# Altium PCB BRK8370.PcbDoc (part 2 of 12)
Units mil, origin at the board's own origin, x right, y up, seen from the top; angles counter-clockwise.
Board outline 8267.72 x 5708.66 mil, 6 copper layers (L1-TOP, L2-GND, L3-PWR, L4-PWR, L5-GND, L6-BOT), stack 68.606 mil thick; 319 components, 516 nets, 2008 pads, 1743 vias.
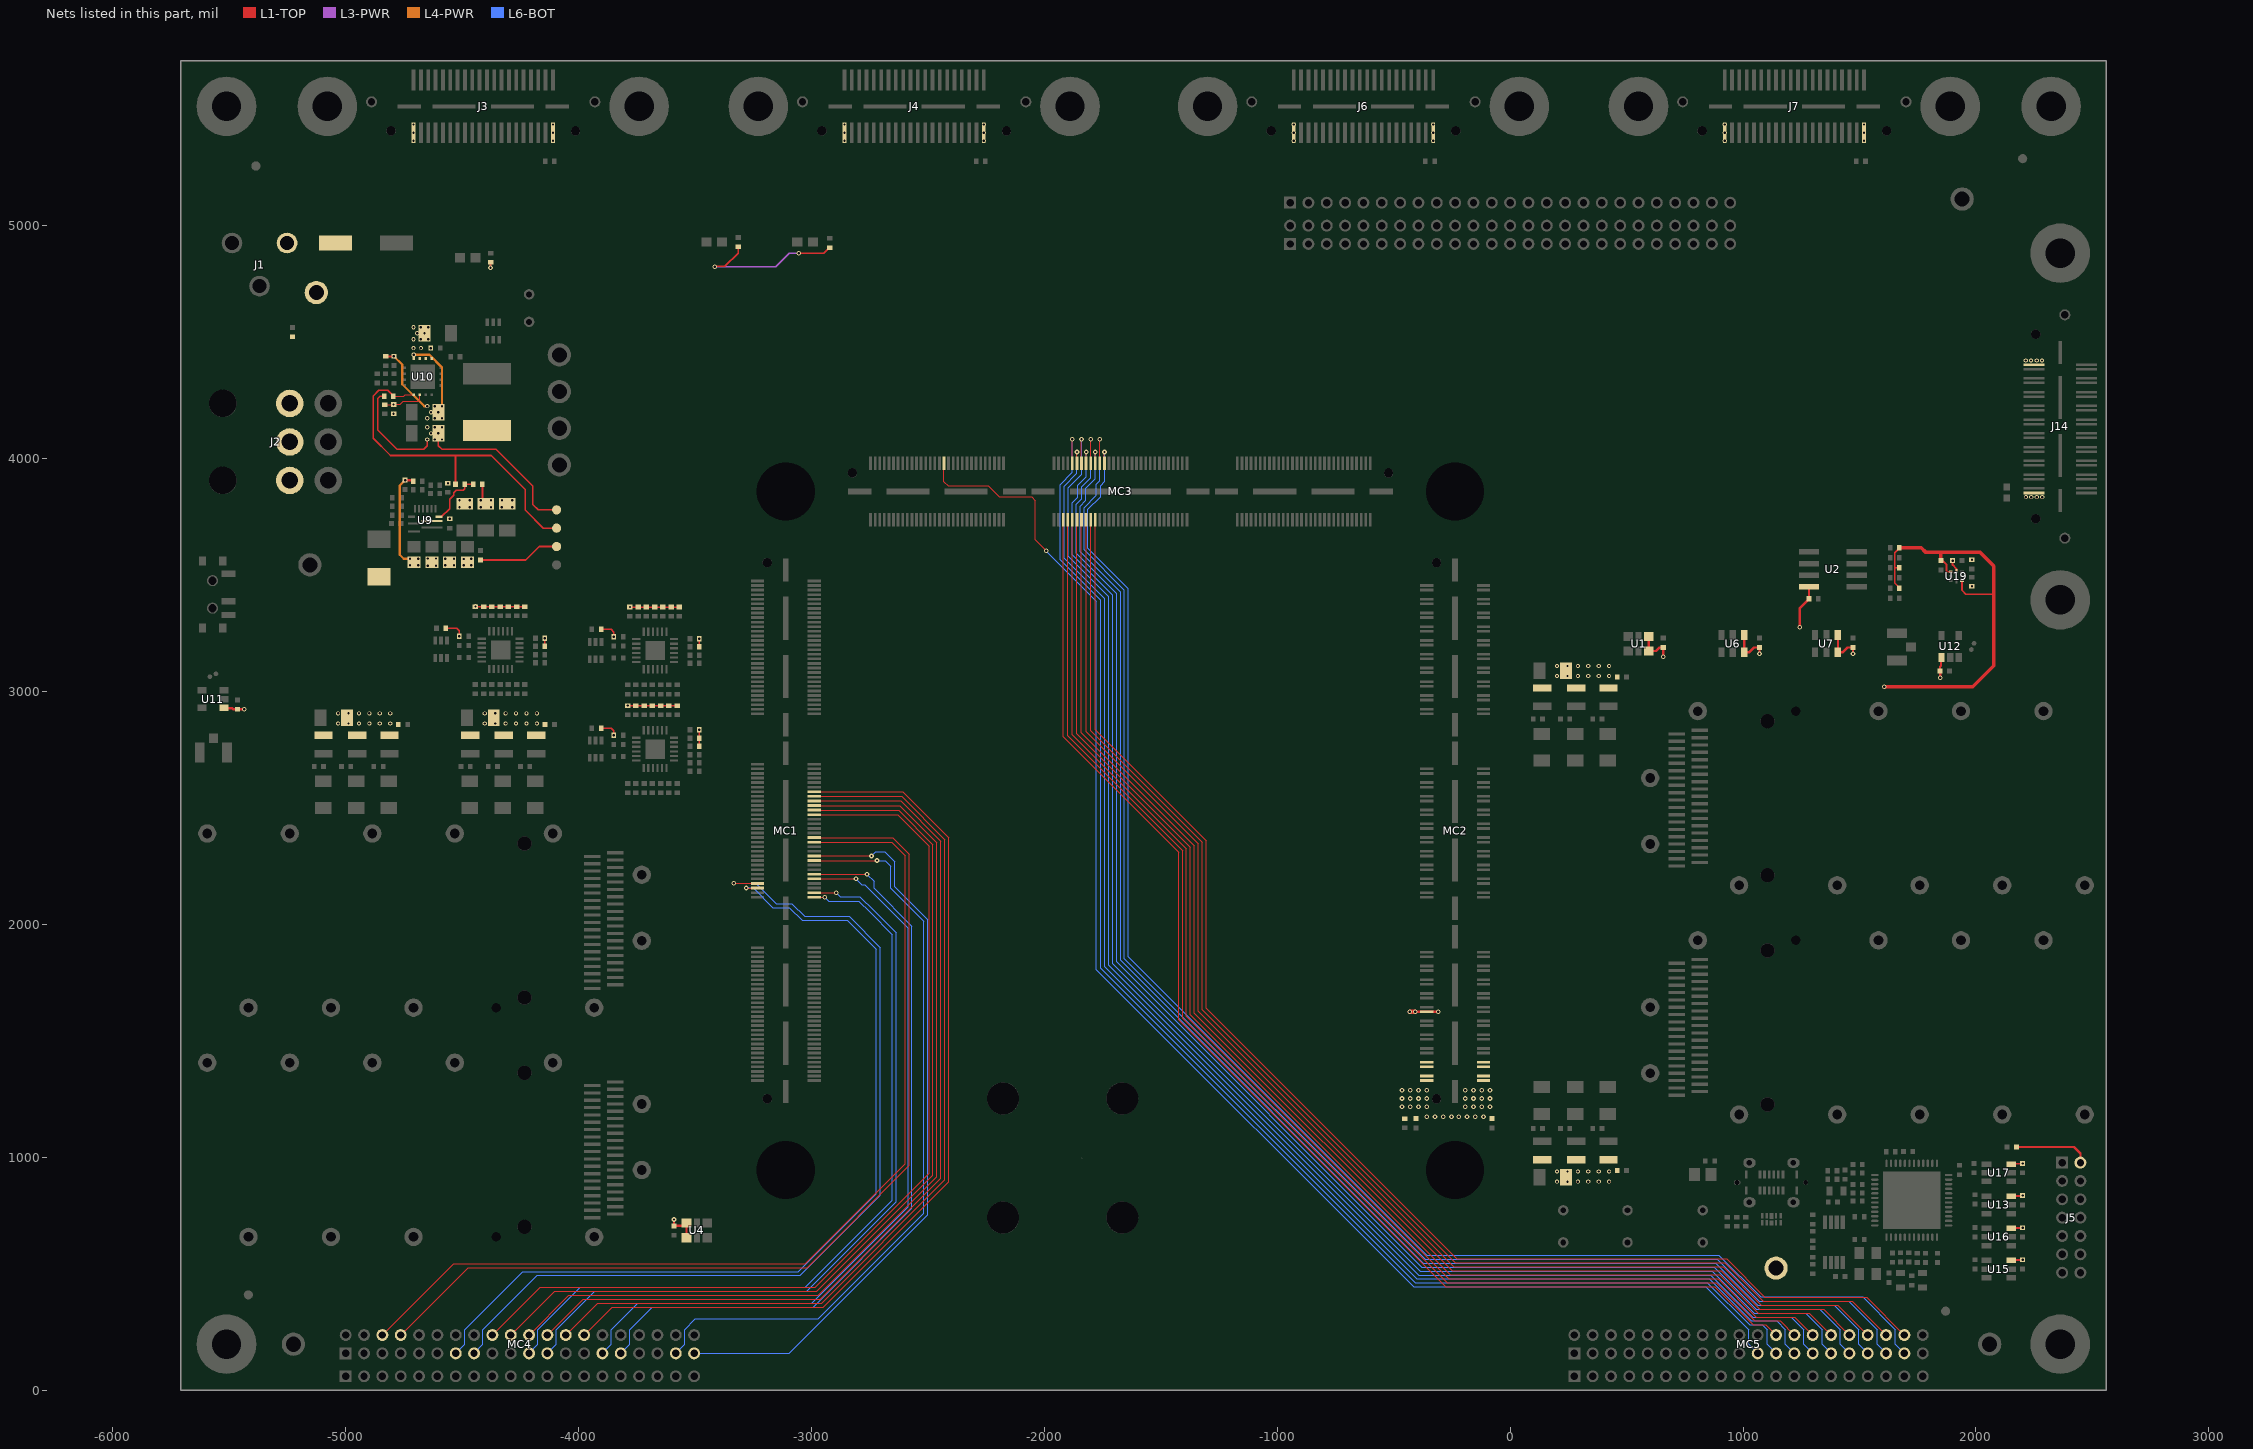
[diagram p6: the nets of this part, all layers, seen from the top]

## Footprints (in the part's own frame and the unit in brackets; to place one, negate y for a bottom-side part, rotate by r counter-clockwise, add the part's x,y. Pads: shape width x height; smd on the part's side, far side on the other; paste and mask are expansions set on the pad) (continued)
okLogo-23x5-2021 [mil] "Opal Kelly silkscreen logo (23mm x 5mm) - 2021 update"
  silkscreen extent -4,-15 672,100
OSC_SMD_32x25_6pin [mm] "3.2x2.5mm SMD clock oscillator"
  rect 0.7x1.05 smd: 1(-1.25,-0.95) 2(0,-0.95) 3(1.25,-0.95) 4(1.25,0.95) 5(0,0.95) 6(-1.25,0.95)
  silkscreen extent -1.8,-1.68 1.8,1.2
QFN-24 [mm] "QFN, 24-Leads, Body 4x4mm, Pitch 0.5mm"
  rect 2.1x2.1 smd paste-1.2: 0(0,0)
  rect 0.9x0.24 smd: 1(-2.05,1.25) 2(-2.05,0.75) 3(-2.05,0.25) 4(-2.05,-0.25) 5(-2.05,-0.75) 6(-2.05,-1.25) 13(2.05,-1.25) 14(2.05,-0.75) 15(2.05,-0.25) 16(2.05,0.25) 17(2.05,0.75) 18(2.05,1.25)
  rect 0.24x0.9 smd: 7(-1.25,-2.05) 8(-0.75,-2.05) 9(-0.25,-2.05) 10(0.25,-2.05) 11(0.75,-2.05) 12(1.25,-2.05) 19(1.25,2.05) 20(0.75,2.05) 21(0.25,2.05) 22(-0.25,2.05) 23(-0.75,2.05) 24(-1.25,2.05)
  silkscreen extent -2.69,-2.17 2.17,2.69, body extent -2.07,-2.07 2.07,2.07, height 0.8
QSE-020-01-X-D-A-L-SYZYGY [mil]
  rect 100x17 smd paste+0: 0(-317.45,0) 0(317.55,0)
  rect 185x17 smd paste+0: 0(-124.95,0) 0(125.05,0)
  rect 16x89.5 smd paste+0: 1(-299.25,-112.8) 2(-299.25,112.8) 3(-267.75,-112.8) 4(-267.75,112.8) 5(-236.25,-112.8) 6(-236.25,112.8) 7(-204.75,-112.8) 8(-204.75,112.8) 9(-173.25,-112.8) 10(-173.25,112.8) 11(-141.75,-112.8) 12(-141.75,112.8) 13(-110.25,-112.8) 14(-110.25,112.8) 15(-78.75,-112.8) 16(-78.75,112.8) 17(-47.25,-112.8) 18(-47.25,112.8) 19(-15.75,-112.8) 20(-15.75,112.8) 21(15.75,-112.8) 22(15.75,112.8) 23(47.25,-112.8) 24(47.25,112.8) 25(78.75,-112.8) 26(78.75,112.8) 27(110.25,-112.8) 28(110.25,112.8) 29(141.75,-112.8) 30(141.75,112.8) 31(173.25,-112.8) 32(173.25,112.8) 33(204.75,-112.8) 34(204.75,112.8) 35(236.25,-112.8) 36(236.25,112.8) 37(267.75,-112.8) 38(267.75,112.8) 39(299.25,-112.8) 40(299.25,112.8)
  round 47.24 hole 31.5 paste+0: MH(-479.48,-19.68) MH(479.58,-19.68)
  round 40.16 hole 40.16 unplated paste+0: MH(-396.25,105) MH(396.35,105)
  round 255.91 hole 125.98: NC(-669.24,0) NC(669.34,0)
  silkscreen extent -886,-157 885,276
QSFP28_RECEPTACLE_SFF-8679 [mm]
  rect 0.35x1.8 smd: 1(1.4,7.37) 2(2.2,7.37) 3(3,7.37) 4(3.8,7.37) 5(4.6,7.37) 6(5.4,7.37) 7(6.2,7.37) 8(7,7.37) 9(7.8,7.37) 10(8.6,7.37) 11(9.4,7.37) 12(10.2,7.37) 13(11,7.37) 14(11.8,7.37) 15(12.6,7.37) 16(13.4,7.37) 17(14.2,7.37) 18(15,7.37) 19(15.8,7.37) 20(15.4,9.88) 21(14.6,9.88) 22(13.8,9.88) 23(13,9.88) 24(12.2,9.88) 25(11.4,9.88) 26(10.6,9.88) 27(9.8,9.88) 28(9,9.88) 29(8.2,9.88) 30(7.4,9.88) 31(6.6,9.88) 32(5.8,9.88) 33(5,9.88) 34(4.2,9.88) 35(3.4,9.88) 36(2.6,9.88) 37(1.8,9.88) 38(1,9.88)
  round 1.55 hole 1.55 unplated: MH(0,0) MH(16.8,0)
  L1-TOP keep-out region: -0.5,-3.16 0.5,-3.16 0.5,-2.16 -0.5,-2.16
  L1-TOP keep-out region: 16.3,-3.16 17.3,-3.16 17.3,-2.16 16.3,-2.16
  silkscreen extent -0.8,-3 17.6,9.7
QSFP28_SINGLE_CAGE [mm]
  round 2 hole 1.05: 0(-1.1,3.1) 0(-1.1,-7.6) 0(-1.1,-16.6) 0(-1.1,-25.6) 0(-1.1,-34.6) 0(3.4,12.79) 0(10.6,12.79) 0(17.9,7.6) 0(17.9,-21.1) 0(17.9,-12.1) 0(17.9,-30.1)
  round 0 hole 1.05 unplated: 0(17.9,-3.1)
  L1-TOP keep-out region: -2.7,13.5 -2.7,-37 19.5,-37 19.5,13.5 16.5,13.5 16.5,11.1 18,11.1 18,-1.6 15.9,-1.6 15.9,-3.5 0.9,-3.5 0.9,-1.6 -1.2,-1.6 -1.2,11.1 0.3,11.1 0.3,13.5
  silkscreen extent -1.1,-48.2 17.9,12.9
QSH-020-01-X-D-DP-A-L-SYZYGY [mm]
  rect 2.54x0.43 smd mask+0.051: 0(-8.07,0) 0(8.06,0)
  rect 4.7x0.43 smd mask+0.051: 0(-3.18,0) 0(3.17,0)
  round 6.5 hole 3.2: 1(-18.909,0) 1(18.911,0)
  rect 0.28x2.27 smd mask+0.051: 1(-7.25,-2.87) 2(-7.25,2.87) 3(-6.75,-2.87) 4(-6.75,2.87) 5(-5.75,-2.87) 6(-5.75,2.87) 7(-5.25,-2.87) 8(-5.25,2.87) 9(-4.25,-2.87) 10(-4.25,2.87) 11(-3.75,-2.87) 12(-3.75,2.87) 13(-2.75,-2.87) 14(-2.75,2.87) 15(-2.25,-2.87) 16(-2.25,2.87) 17(-1.25,-2.87) 18(-1.25,2.87) 19(-0.75,-2.87) 20(-0.75,2.87) 21(0.25,-2.87) 22(0.25,2.87) 23(0.75,-2.87) 24(0.75,2.87) 25(1.75,-2.87) 26(1.75,2.87) 27(2.25,-2.87) 28(2.25,2.87) 29(3.25,-2.87) 30(3.25,2.87) 31(3.75,-2.87) 32(3.75,2.87) 33(4.75,-2.87) 34(4.75,2.87) 35(5.25,-2.87) 36(5.25,2.87) 37(6.25,-2.87) 38(6.25,2.87) 39(6.75,-2.87) 40(6.75,2.87)
  round 1.2 hole 0.8 paste+0 mask+0.076: MH(-12.18,-0.5) MH(12.18,-0.5)
  round 1.02 hole 1.02 unplated paste+0: MH(-10.07,2.67) MH(10.07,2.67)
  silkscreen extent -25,-3.99 25,7.01
QTH-060-01-X-D-DP-A [mm]
  rect 2.54x0.64 smd: 0(-28.445,0) 0(-11.555,0) 0(-8.445,0) 0(8.445,0) 0(11.555,0) 0(28.445,0)
  rect 4.7x0.64 smd: 0(-23.175,0) 0(-16.825,0) 0(-3.175,0) 0(3.175,0) 0(16.825,0) 0(23.175,0)
  rect 0.3x1.45 smd: 1(-27.25,3.09) 2(-27.25,-3.09) 3(-26.75,3.09) 4(-26.75,-3.09) 5(-25.75,3.09) 6(-25.75,-3.09) 7(-25.25,3.09) 8(-25.25,-3.09) 9(-24.25,3.09) 10(-24.25,-3.09) 11(-23.75,3.09) 12(-23.75,-3.09) 13(-22.75,3.09) 14(-22.75,-3.09) 15(-22.25,3.09) 16(-22.25,-3.09) 17(-21.25,3.09) 18(-21.25,-3.09) 19(-20.75,3.09) 20(-20.75,-3.09) 21(-19.75,3.09) 22(-19.75,-3.09) 23(-19.25,3.09) 24(-19.25,-3.09) 25(-18.25,3.09) 26(-18.25,-3.09) 27(-17.75,3.09) 28(-17.75,-3.09) 29(-16.75,3.09) 30(-16.75,-3.09) 31(-16.25,3.09) 32(-16.25,-3.09) 33(-15.25,3.09) 34(-15.25,-3.09) 35(-14.75,3.09) 36(-14.75,-3.09) 37(-13.75,3.09) 38(-13.75,-3.09) 39(-13.25,3.09) 40(-13.25,-3.09) 41(-7.25,3.09) 42(-7.25,-3.09) 43(-6.75,3.09) 44(-6.75,-3.09) 45(-5.75,3.09) 46(-5.75,-3.09) 47(-5.25,3.09) 48(-5.25,-3.09) 49(-4.25,3.09) 50(-4.25,-3.09) 51(-3.75,3.09) 52(-3.75,-3.09) 53(-2.75,3.09) 54(-2.75,-3.09) 55(-2.25,3.09) 56(-2.25,-3.09) 57(-1.25,3.09) 58(-1.25,-3.09) 59(-0.75,3.09) 60(-0.75,-3.09) 61(0.25,3.09) 62(0.25,-3.09) 63(0.75,3.09) 64(0.75,-3.09) 65(1.75,3.09) 66(1.75,-3.09) 67(2.25,3.09) 68(2.25,-3.09) 69(3.25,3.09) 70(3.25,-3.09) 71(3.75,3.09) 72(3.75,-3.09) 73(4.75,3.09) 74(4.75,-3.09) 75(5.25,3.09) 76(5.25,-3.09) 77(6.25,3.09) 78(6.25,-3.09) 79(6.75,3.09) 80(6.75,-3.09) 81(12.75,3.09) 82(12.75,-3.09) 83(13.25,3.09) 84(13.25,-3.09) 85(14.25,3.09) 86(14.25,-3.09) 87(14.75,3.09) 88(14.75,-3.09) 89(15.75,3.09) 90(15.75,-3.09) 91(16.25,3.09) 92(16.25,-3.09) 93(17.25,3.09) 94(17.25,-3.09) 95(17.75,3.09) 96(17.75,-3.09) 97(18.75,3.09) 98(18.75,-3.09) 99(19.25,3.09) 100(19.25,-3.09) 101(20.25,3.09) 102(20.25,-3.09) 103(20.75,3.09) 104(20.75,-3.09) 105(21.75,3.09) 106(21.75,-3.09) 107(22.25,3.09) 108(22.25,-3.09) 109(23.25,3.09) 110(23.25,-3.09) 111(23.75,3.09) 112(23.75,-3.09) 113(24.75,3.09) 114(24.75,-3.09) 115(25.25,3.09) 116(25.25,-3.09) 117(26.25,3.09) 118(26.25,-3.09) 119(26.75,3.09) 120(26.75,-3.09)
  round 1.02 hole 1.02 unplated: MH(-29.24,2.03) MH(29.24,2.03)
  silkscreen extent -30.05,-3.05 30.05,3.05
QTH-090-01-X-D [mm]
  rect 2.54x0.64 smd: 0(-28.445,0) 0(-11.555,0) 0(-8.445,0) 0(8.445,0) 0(11.555,0) 0(28.445,0)
  rect 4.7x0.64 smd: 0(-23.175,0) 0(-16.825,0) 0(-3.175,0) 0(3.175,0) 0(16.825,0) 0(23.175,0)
  rect 0.3x1.45 smd: 1(-27.25,3.09) 2(-27.25,-3.09) 3(-26.75,3.09) 4(-26.75,-3.09) 5(-26.25,3.09) 6(-26.25,-3.09) 7(-25.75,3.09) 8(-25.75,-3.09) 9(-25.25,3.09) 10(-25.25,-3.09) 11(-24.75,3.09) 12(-24.75,-3.09) 13(-24.25,3.09) 14(-24.25,-3.09) 15(-23.75,3.09) 16(-23.75,-3.09) 17(-23.25,3.09) 18(-23.25,-3.09) 19(-22.75,3.09) 20(-22.75,-3.09) 21(-22.25,3.09) 22(-22.25,-3.09) 23(-21.75,3.09) 24(-21.75,-3.09) 25(-21.25,3.09) 26(-21.25,-3.09) 27(-20.75,3.09) 28(-20.75,-3.09) 29(-20.25,3.09) 30(-20.25,-3.09) 31(-19.75,3.09) 32(-19.75,-3.09) 33(-19.25,3.09) 34(-19.25,-3.09) 35(-18.75,3.09) 36(-18.75,-3.09) 37(-18.25,3.09) 38(-18.25,-3.09) 39(-17.75,3.09) 40(-17.75,-3.09) 41(-17.25,3.09) 42(-17.25,-3.09) 43(-16.75,3.09) 44(-16.75,-3.09) 45(-16.25,3.09) 46(-16.25,-3.09) 47(-15.75,3.09) 48(-15.75,-3.09) 49(-15.25,3.09) 50(-15.25,-3.09) 51(-14.75,3.09) 52(-14.75,-3.09) 53(-14.25,3.09) 54(-14.25,-3.09) 55(-13.75,3.09) 56(-13.75,-3.09) 57(-13.25,3.09) 58(-13.25,-3.09) 59(-12.75,3.09) 60(-12.75,-3.09) 61(-7.25,3.09) 62(-7.25,-3.09) 63(-6.75,3.09) 64(-6.75,-3.09) 65(-6.25,3.09) 66(-6.25,-3.09) 67(-5.75,3.09) 68(-5.75,-3.09) 69(-5.25,3.09) 70(-5.25,-3.09) 71(-4.75,3.09) 72(-4.75,-3.09) 73(-4.25,3.09) 74(-4.25,-3.09) 75(-3.75,3.09) 76(-3.75,-3.09) 77(-3.25,3.09) 78(-3.25,-3.09) 79(-2.75,3.09) 80(-2.75,-3.09) 81(-2.25,3.09) 82(-2.25,-3.09) 83(-1.75,3.09) 84(-1.75,-3.09) 85(-1.25,3.09) 86(-1.25,-3.09) 87(-0.75,3.09) 88(-0.75,-3.09) 89(-0.25,3.09) 90(-0.25,-3.09) 91(0.25,3.09) 92(0.25,-3.09) 93(0.75,3.09) 94(0.75,-3.09) 95(1.25,3.09) 96(1.25,-3.09) 97(1.75,3.09) 98(1.75,-3.09) 99(2.25,3.09) 100(2.25,-3.09) 101(2.75,3.09) 102(2.75,-3.09) 103(3.25,3.09) 104(3.25,-3.09) 105(3.75,3.09) 106(3.75,-3.09) 107(4.25,3.09) 108(4.25,-3.09) 109(4.75,3.09) 110(4.75,-3.09) 111(5.25,3.09) 112(5.25,-3.09) 113(5.75,3.09) 114(5.75,-3.09) 115(6.25,3.09) 116(6.25,-3.09) 117(6.75,3.09) 118(6.75,-3.09) 119(7.25,3.09) 120(7.25,-3.09) 121(12.75,3.09) 122(12.75,-3.09) 123(13.25,3.09) 124(13.25,-3.09) 125(13.75,3.09) 126(13.75,-3.09) 127(14.25,3.09) 128(14.25,-3.09) 129(14.75,3.09) 130(14.75,-3.09) 131(15.25,3.09) 132(15.25,-3.09) 133(15.75,3.09) 134(15.75,-3.09) 135(16.25,3.09) 136(16.25,-3.09) 137(16.75,3.09) 138(16.75,-3.09) 139(17.25,3.09) 140(17.25,-3.09) 141(17.75,3.09) 142(17.75,-3.09) 143(18.25,3.09) 144(18.25,-3.09) 145(18.75,3.09) 146(18.75,-3.09) 147(19.25,3.09) 148(19.25,-3.09) 149(19.75,3.09) 150(19.75,-3.09) 151(20.25,3.09) 152(20.25,-3.09) 153(20.75,3.09) 154(20.75,-3.09) 155(21.25,3.09) 156(21.25,-3.09) 157(21.75,3.09) 158(21.75,-3.09) 159(22.25,3.09) 160(22.25,-3.09) 161(22.75,3.09) 162(22.75,-3.09) 163(23.25,3.09) 164(23.25,-3.09) 165(23.75,3.09) 166(23.75,-3.09) 167(24.25,3.09) 168(24.25,-3.09) 169(24.75,3.09) 170(24.75,-3.09) 171(25.25,3.09) 172(25.25,-3.09) 173(25.75,3.09) 174(25.75,-3.09) 175(26.25,3.09) 176(26.25,-3.09) 177(26.75,3.09) 178(26.75,-3.09) 179(27.25,3.09) 180(27.25,-3.09)
  round 1.02 hole 1.02 unplated: MH(-29.24,2.03) MH(29.24,2.03)
  silkscreen extent -30.05,-3.05 30.05,3.05
RESC1005N [mm] "Chip Resistor, Body 1.1x0.5mm, IPC Medium Density"
  rect 0.8x0.7 smd: 1(-0.6,0) 2(0.6,0)
  silkscreen extent -0.5,-0.53 0.5,0.53, body extent -0.55,-0.3 0.55,0.3, height 0.4
RESC1005X06A [mm] "Chip Resistor, 2-Leads, Body 1.00x0.50mm, OK custom footprint"
  rect 0.5x0.6 smd mask+0.051: 1(-0.5,0) 2(0.5,0)
RESC2012N [mm] "Chip Resistor, Body 2.0x1.3mm, IPC Medium Density"
  rect 1.2x1.4 smd: 1(-0.9,0) 2(0.9,0)
  silkscreen extent -0.85,-0.89 0.85,0.88, body extent -1.07,-0.7 1.07,0.7, height 0.65
RT6278 [mm]
  rect 0.8x0.23 smd: 1(-1.5,0.619) 6(1.5,0.619)
  rect 1.35x0.23 smd: 2(-1.225,-0.101) 3(-1.225,-1.001)
  rect 2.28x0.23 smd: 4(0.76,-0.551) 5(0.76,0.169)
  rect 0.23x0.8 smd: 7(1.125,1.5) 8(0.675,1.5) 9(0.225,1.5) 10(-0.225,1.5) 11(-0.675,1.5) 12(-1.125,1.5)
  silkscreen extent -2,-1.55 1.55,2
SIT9120AX-XB [mm]
  rect 1.05x1 smd: 1(-1.125,-0.8) 3(1.125,-0.8) 4(1.125,0.8) 6(-1.125,0.8)
  rect 0.65x1 smd: 2(0,-0.8) 5(0,0.8)
  silkscreen extent -1.85,-1.5 1.85,1.2
SO-G8 [mm] "Small Outline; 8 Leads; Body Width 3.9 mm; Pitch 1.27 mm"
  rect 0.6x2.2 smd: 1(-1.905,-2.6) 2(-0.635,-2.6) 3(0.635,-2.6) 4(1.905,-2.6) 5(1.905,2.6) 6(0.635,2.6) 7(-0.635,2.6) 8(-1.905,2.6)
  silkscreen extent -2.45,-3.7 2.45,1.95
SOT23-5 [mm] "SOT-23; 5 Leads; Body 2.9 x 2.5 mm, inc. leads (LxW max)"
  rect 0.7x1 smd: 1(-0.95,-1.2) 2(0,-1.2) 3(0.95,-1.2) 4(0.95,1.2) 5(-0.95,1.2)
  silkscreen extent -1.5,-1.7 1.5,0.75
SOT23-6 [mm] "SOT-23; 6 Leads; Body 3.05 x 1.75 mm, inc. leads (LxW max)"
  rect 0.6x1.05 smd: 1(-0.95,-1.35) 2(0,-1.35) 3(0.95,-1.35) 4(0.95,1.35) 5(0,1.35) 6(-0.95,1.35)
  silkscreen extent -1.5,-1.9 1.5,0.75
SOT363-6N [mm] "SOT363, 6-Leads, Body 2x1.3mm, Pitch 0.65mm, Lead Span 2.1mm, IPC Medium Density"
  rect 0.85x0.4 smd: 1(-0.95,0.65) 2(-0.95,0) 3(-0.95,-0.65) 4(0.95,-0.65) 5(0.95,0) 6(0.95,0.65)
  silkscreen extent -1.37,-1.09 0.63,1.09, body extent -0.63,-1 0.63,1, height 1
SSSS811101 [mm] "Surface mount, 1 position, 2 pole switch"
  rect 1x0.8 smd: 0(-3.65,-1.1) 0(-3.65,1.1) 0(3.65,-1.1) 0(3.65,1.1)
  round 1.2 hole 0.9: 0(-1.5,0) 0(1.5,0)
  rect 0.7x1.5 smd: 1(-2.25,1.75) 2(0.75,1.75) 3(2.25,1.75)
  silkscreen extent -3.35,-2.8 3.35,1.3
Switch-PCB-wMounts [mm]
  round 3.5 hole 3.5 unplated paste-0.02 mask+0.02: 0(-6.5,-6.5) 0(-6.5,6.5) 0(6.5,-6.5) 0(6.5,6.5)
  round 4.5 on Top Solder: 0(0,0)
  round 0.025 smd paste-1 mask-1: 1(-2.1,0) 2(2.1,0.001)
  L1-TOP region: -0.672,-1.601 -0.664,-1.639 -0.642,-1.672 -0.61,-1.693 -0.572,-1.701 -0.572,-1.701 1.016,-1.701 0.657,-1.871 0.271,-1.967 0.271,-1.967 0.214,-1.982 0.17,-2.022 0.15,-2.077 0.159,-2.136 0.193,-2.183 0.246,-2.209 0.305,-2.208 0.305,-2.208 1.28,-1.829 1.97,-1.043 2.219,-0.027 2.219,-0.027 1.993,1.009 1.306,1.817 0.32,2.206 0.32,2.206 0.262,2.208 0.21,2.184 0.174,2.139 0.163,2.082 0.178,2.026 0.217,1.984 0.271,1.963 0.271,1.963 0.659,1.87 1.021,1.7 1.021,1.7 -0.6,1.7 -0.643,1.69 -0.678,1.662 -0.697,1.622 -0.697,1.578 -0.678,1.538 -0.643,1.51 -0.6,1.5 -0.6,1.5 1.297,1.5 1.561,1.222 1.767,0.899 1.767,0.899 -1.372,0.899 -1.415,0.889 -1.45,0.861 -1.469,0.821 -1.469,0.777 -1.45,0.737 -1.415,0.709 -1.372,0.699 -1.372,0.699 1.855,0.699 1.94,0.404 1.978,0.099 1.978,0.099 -1.572,0.099 -1.615,0.089 -1.65,0.061 -1.669,0.021 -1.669,-0.023 -1.65,-0.063 -1.615,-0.091 -1.572,-0.101 -1.572,-0.101 1.977,-0.101 1.937,-0.406 1.85,-0.701 1.85,-0.701 -1.472,-0.701 -1.515,-0.711 -1.55,-0.739 -1.569,-0.779 -1.569,-0.823 -1.55,-0.863 -1.515,-0.891 -1.472,-0.901 -1.472,-0.901 1.761,-0.901 1.555,-1.224 1.291,-1.501 1.291,-1.501 -0.572,-1.501 -0.61,-1.509 -0.642,-1.53 -0.664,-1.563 -0.672,-1.601
  L1-TOP region: 1.213,-1.295 1.256,-1.285 1.291,-1.257 1.31,-1.217 1.31,-1.172 1.291,-1.132 1.256,-1.105 1.213,-1.095 1.213,-1.095 -1.648,-1.095 -1.806,-0.808 -1.915,-0.5 -1.915,-0.5 1.614,-0.5 1.657,-0.49 1.692,-0.462 1.711,-0.422 1.711,-0.378 1.692,-0.337 1.657,-0.31 1.614,-0.3 1.614,-0.3 -1.956,-0.3 -1.974,-0.153 -1.98,-0.005 -1.98,-0.005 -1.975,0.148 -1.958,0.301 -1.958,0.301 1.622,0.301 1.665,0.311 1.7,0.339 1.719,0.379 1.719,0.423 1.7,0.463 1.665,0.491 1.622,0.501 1.622,0.501 -1.917,0.501 -1.808,0.812 -1.649,1.1 -1.649,1.1 1.2,1.1 1.243,1.11 1.278,1.138 1.297,1.178 1.297,1.222 1.278,1.262 1.243,1.29 1.2,1.3 1.2,1.3 -1.497,1.3 -0.944,1.743 -0.271,1.963 -0.271,1.963 -0.217,1.984 -0.178,2.026 -0.163,2.082 -0.174,2.139 -0.21,2.184 -0.262,2.208 -0.32,2.206 -0.32,2.206 -1.306,1.817 -1.993,1.009 -2.219,-0.027 -2.219,-0.027 -1.97,-1.043 -1.28,-1.829 -0.305,-2.208 -0.305,-2.208 -0.246,-2.209 -0.193,-2.183 -0.159,-2.136 -0.15,-2.077 -0.17,-2.022 -0.214,-1.982 -0.271,-1.967 -0.271,-1.967 -0.944,-1.742 -1.497,-1.295 -1.497,-1.295
TP-PTH-25/45 [mil] "Test point, plated through-hole, 25/45mil"
  round 45 hole 25: 1(0,0)
TP-PTH-65/100 [mil] "Test point, plated through-hole, 65/100mil"
  round 100 hole 65: 1(0,0)
TP-SMD20 [mil] "Test point, surface-mount, 20mil"
  round 20 smd paste-78.74: 1(0,0)
TP-SMD40 [mm] "Test point, surface-mount, 40mil"
  round 1 smd paste-2: 1(0,0)
TPS54429E [mm]
  rect 0.3x0.3 smd paste-10 mask-10: 1(-1.975,0.975)
  rect 0.3x0.3 smd: 2(-1.975,0.325) 3(-1.975,-0.325) 4(-1.975,-0.975) 5(-0.975,-1.975) 6(-0.325,-1.975) 7(0.325,-1.975) 8(0.975,-1.975) 9(1.975,-0.975) 10(1.975,-0.325) 11(1.975,0.325) 12(1.975,0.975) 13(0.975,1.975) 14(0.325,1.975) 15(-0.325,1.975) 16(-0.975,1.975)
  rect 2.7x2.7 smd paste-10: PAD(0,0)
  L1-TOP region: 2.4,-1.15 1.725,-1.15 1.658,-1.137 1.601,-1.099 1.563,-1.042 1.55,-0.975 1.55,-0.975 1.563,-0.908 1.601,-0.851 1.658,-0.813 1.725,-0.8 1.725,-0.8 2.4,-0.8
  L1-TOP region: -2.4,1.15 -1.725,1.15 -1.658,1.137 -1.601,1.099 -1.563,1.042 -1.55,0.975 -1.55,0.975 -1.563,0.908 -1.601,0.851 -1.658,0.813 -1.725,0.8 -1.725,0.8 -2.4,0.8
  L1-TOP region: -2.4,0.5 -1.725,0.5 -1.658,0.487 -1.601,0.449 -1.563,0.392 -1.55,0.325 -1.55,0.325 -1.563,0.258 -1.601,0.201 -1.658,0.163 -1.725,0.15 -1.725,0.15 -2.4,0.15
  L1-TOP region: -2.4,-0.15 -1.725,-0.15 -1.658,-0.163 -1.601,-0.201 -1.563,-0.258 -1.55,-0.325 -1.55,-0.325 -1.563,-0.392 -1.601,-0.449 -1.658,-0.487 -1.725,-0.5 -1.725,-0.5 -2.4,-0.5
  L1-TOP region: -2.4,-0.8 -1.725,-0.8 -1.658,-0.813 -1.601,-0.851 -1.563,-0.908 -1.55,-0.975 -1.55,-0.975 -1.563,-1.042 -1.601,-1.099 -1.658,-1.137 -1.725,-1.15 -1.725,-1.15 -2.4,-1.15
  L1-TOP region: -1.15,-2.4 -1.15,-1.725 -1.137,-1.658 -1.099,-1.601 -1.042,-1.563 -0.975,-1.55 -0.975,-1.55 -0.908,-1.563 -0.851,-1.601 -0.813,-1.658 -0.8,-1.725 -0.8,-1.725 -0.8,-2.4
  L1-TOP region: -0.5,-2.4 -0.5,-1.725 -0.487,-1.658 -0.449,-1.601 -0.392,-1.563 -0.325,-1.55 -0.325,-1.55 -0.258,-1.563 -0.201,-1.601 -0.163,-1.658 -0.15,-1.725 -0.15,-1.725 -0.15,-2.4
  L1-TOP region: 0.15,-2.4 0.15,-1.725 0.163,-1.658 0.201,-1.601 0.258,-1.563 0.325,-1.55 0.325,-1.55 0.392,-1.563 0.449,-1.601 0.487,-1.658 0.5,-1.725 0.5,-1.725 0.5,-2.4
  L1-TOP region: 0.8,-2.4 0.8,-1.725 0.813,-1.658 0.851,-1.601 0.908,-1.563 0.975,-1.55 0.975,-1.55 1.042,-1.563 1.099,-1.601 1.137,-1.658 1.15,-1.725 1.15,-1.725 1.15,-2.4
  L1-TOP region: 2.4,-0.5 1.725,-0.5 1.658,-0.487 1.601,-0.449 1.563,-0.392 1.55,-0.325 1.55,-0.325 1.563,-0.258 1.601,-0.201 1.658,-0.163 1.725,-0.15 1.725,-0.15 2.4,-0.15
  L1-TOP region: 2.4,0.15 1.725,0.15 1.658,0.163 1.601,0.201 1.563,0.258 1.55,0.325 1.55,0.325 1.563,0.392 1.601,0.449 1.658,0.487 1.725,0.5 1.725,0.5 2.4,0.5
  L1-TOP region: 2.4,0.8 1.725,0.8 1.658,0.813 1.601,0.851 1.563,0.908 1.55,0.975 1.55,0.975 1.563,1.042 1.601,1.099 1.658,1.137 1.725,1.15 1.725,1.15 2.4,1.15
  L1-TOP region: 1.15,2.4 1.15,1.725 1.137,1.658 1.099,1.601 1.042,1.563 0.975,1.55 0.975,1.55 0.908,1.563 0.851,1.601 0.813,1.658 0.8,1.725 0.8,1.725 0.8,2.4
  L1-TOP region: 0.5,2.4 0.5,1.725 0.487,1.658 0.449,1.601 0.392,1.563 0.325,1.55 0.325,1.55 0.258,1.563 0.201,1.601 0.163,1.658 0.15,1.725 0.15,1.725 0.15,2.4
  L1-TOP region: -0.15,2.4 -0.15,1.725 -0.163,1.658 -0.201,1.601 -0.258,1.563 -0.325,1.55 -0.325,1.55 -0.392,1.563 -0.449,1.601 -0.487,1.658 -0.5,1.725 -0.5,1.725 -0.5,2.4
  L1-TOP region: -0.8,2.4 -0.8,1.725 -0.813,1.658 -0.851,1.601 -0.908,1.563 -0.975,1.55 -0.975,1.55 -1.042,1.563 -1.099,1.601 -1.137,1.658 -1.15,1.725 -1.15,1.725 -1.15,2.4
  L1-TOP keep-out region: -2,1.5 -1.5,1.5 -1.5,2 -2,2
  silkscreen extent -2.35,-2.1 2.1,2.35
UFL-R-SMT-1 [mm] "U.FL surface-mount coaxial connector"
  rect 1x1.05 smd paste+0: 1(0,-1.525)
  rect 1.05x2.2 smd paste+0: 2(-1.475,0) 2(1.475,0)
  silkscreen extent -1.3,-1.3 1.3,1.3
USB4120-03-C [mm]
  rect 0.3x0.87 smd: A1(-2.75,0.865) A4(-1.25,0.865) A5(-0.75,0.865) A6(-0.25,0.865) A7(0.25,0.865) A8(0.75,0.865) A9(1.25,0.865) A12(2.75,0.865) B1(2.75,-0.865) B4(1.25,-0.865) B5(0.75,-0.865) B6(0.25,-0.865) B7(-0.25,-0.865) B8(-0.75,-0.865) B9(-1.25,-0.865) B12(-2.75,-0.865)
  oval 1.35x1.1 hole 0.6 slot 0.85 at 0 deg: M1(-2.4,2.15) M2(2.4,2.15) M3(2.4,-2.15) M4(-2.4,-2.15)
  round 0.52 hole 0.52 unplated paste-20: M5(-3.75,0)
  oval 0.72x0.52 hole 0.52 slot 0.72 at 0 deg unplated paste-20: M6(3.75,0)
  silkscreen extent -4.67,-1.8 4.67,1.8
XILINX-JTAG [mm] "2mm 2x7 header"
  rect 1.3x1.3 hole 0.8: 1(-6,-1)
  round 1.3 hole 0.8: 2(-6,1) 3(-4,-1) 4(-4,1) 5(-2,-1) 6(-2,1) 7(0,-1) 8(0,1) 9(2,-1) 10(2,1) 11(4,-1) 12(4,1) 13(6,-1) 14(6,1)
  silkscreen extent -8.32,-3.15 8.32,3.15

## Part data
C1 C2 C29 C39 C45: library part 001073, "Ceramic capacitor", Manufacturer="Taiyo Yuden", Tolerance (%)=10, ValueFloat=1E-7, Voltage=25V
C3 C4 C5 C6 C8 C10 C12 C13 C15 C17 C20 C21 C23 C25 C30 C31 C32 C33 C34 C51 C52 C77 C90 C92 C95 C102 C104 C107 C112 C114: library part 000070, Manufacturer=Kemet, Manufacturer_PN=C0402C104K8PACTU, ValueFloat=1E-7, x_tolerance=10
C7: library part 000824, Manufacturer="Taiyo Yuden", ValueFloat=4.7E-6, x_tolerance=20
C9 C60 C66 C68: library part 000824, "Ceramic capacitor", Manufacturer="Taiyo Yuden", Tolerance (%)=20, ValueFloat=4.7E-6
C11 C14 C16 C18 C19 C22 C24 C26 C91 C93 C94 C103 C105 C106 C111 C113: library part 001284, Manufacturer="Taiyo Yuden", Manufacturer_PN=LMK316AB7226KL-TR, ValueFloat=2.2E-5, x_temperature_characteristic=X7R, x_tolerance=10
C27 C53: library part 000070, Manufacturer=Kemet, ValueFloat=1E-7, x_tolerance=10
C28: library part 001532, "Polarized", Manufacturer=Panasonic, ValueFloat=0.00022, Voltage=25V, x_tolerance=20, x_voltage-rating=25
C35 C36 C37: library part 001284, "Ceramic capacitor", Manufacturer="Taiyo Yuden", Tolerance (%)=10, ValueFloat=2.2E-5, Voltage=10V
C38: library part 000070, Manufacturer=Kemet, ValueFloat=1E-7, Voltage=10V, x_tolerance=10
C40: library part 002342, Manufacturer=Kemet, ValueFloat=6.8E-11, Voltage=50V, x_tolerance=5
C41 C42 C43 C44: library part 001792, Manufacturer="Samsung Electro-Mechanics", ValueFloat=2.2E-5, Voltage=6.3V, x_tolerance=20
C46: library part 002255, Manufacturer="Taiyo Yuden", ValueFloat=1E-6, Voltage=16V, x_tolerance=10, x_voltage-rating=16
C47: library part 001172, Manufacturer=TDK, ValueFloat=2.2E-5, Voltage=35V, x_tolerance=20, x_voltage-rating=35
C48: library part 001073, Manufacturer="Taiyo Yuden", ValueFloat=1E-7, Voltage=25V, x_tolerance=10
C49 C50: library part 001284, Manufacturer="Taiyo Yuden", ValueFloat=2.2E-5, Voltage=10V, x_tolerance=10
C54: library part 001297, Manufacturer=Kemet, ValueFloat=1E-11, x_tolerance=5, x_voltage-rating=50
C55: library part 001277, Manufacturer=Kemet, ValueFloat=3.3E-9, x_tolerance=10, x_voltage-rating=50
C56: library part 000480, Manufacturer="Taiyo Yuden", ValueFloat=1E-6, x_tolerance=10
C57 C58 C59 C61 C62 C63 C64 C67 C69 C70 C71 C72 C73 C74 C75 C80 C81 C82: library part 000070, Manufacturer=Kemet, Tolerance (%)=10, ValueFloat=1E-7
C65 C76: library part 000295, "Ceramic Capacitor", Manufacturer=Kemet, Tolerance (%)=10, ValueFloat=1E-8
C78 C79: library part 001640, "Ceramic capacitor", Manufacturer=Kemet, Tolerance (%)=5, ValueFloat=1.8E-11, Voltage=50
C128 C129: library part 000070, "Ceramic capacitor", Manufacturer=Kemet, Tolerance (%)=10, ValueFloat=1E-7
D1 D2 D3: library part 001433, "LED", Manufacturer=Dialight, Manufacturer_PN=598-8070-107F
D4: library part 002405, "4 channel TVS diode array", Manufacturer="Diodes Incorporated"
FB1 FB2 FB3: library part 000569, "Ferrite bead", Manufacturer=Steward, ValueFloat=600
FB4: library part 000783, "Ferrite Chip", Manufacturer=Murata, ValueFloat=220
FID1 FID2 FID3 FID4: "PCB fiducial", partnumber=ALIGNI_IGNORE
J1: library part DCPOWER, "DC power connector - high current", Manufacturer="CUI Inc.", partnumber=000356
J2: library part 001950, Manufacturer=Molex
J3 J4 J6 J7: library part 001604, "0.8mm hi-speed, high-density header (male)", Manufacturer=Samtec
J5: library part 000541, "2mm header, shrouded", Manufacturer=Molex
J8 J9 J30 J31: library part 001782, Manufacturer=Amphenol
J10 J12: library part 001335, "U.FL surface-mount coaxial connector", Manufacturer=Hirose, Manufacturer_PN=U.FL-R-SMT-1
J11: library part 002404, "USB 2.0 Type-C receptacle vertical-mount", Manufacturer=GCT
J14: library part 000694, "0.5mm Double Row High Speed Socket Assembly", Manufacturer=Samtec
J15 J16: library part 001334, Manufacturer=3M, Manufacturer_PN=951120-8622-AR
J17: library part 002533, Manufacturer=3M, Manufacturer_PN=951125-8622-AR
JP3: library part 000231, "Slide", Manufacturer=Alps
JSO1 JSO2 JSO3 JSO4: library part 001879, "Mounting hole", Manufacturer=Samtec, Manufacturer_PN=JSO-0515-01
L1 L2 L3 L4 L5 L6 L7 L8 L9 L10 L11 L12: library part 002331, "Thin Film, 1uH, 3.1A, 50mOhm, Unshielded", Manufacturer="Samsung Electro-Mechanics", Tolerance (%)=20, ValueFloat=1E-6
L13: library part 002344, Manufacturer=Sumida, ValueFloat=1.5E-6, x_tolerance=20
L14: library part 002116, Manufacturer=Murata, Manufacturer_PN=1267AY-3R3N{}P3, ValueFloat=3.3E-6, x_tolerance=30
LOGO1: library part OKLOGO, partnumber=ALIGNI_IGNORE
MC1 MC3: library part 000876, "0.5mm hi-speed, high-density header (Female)", Manufacturer=Samtec
MC2: library part 001769, Manufacturer=Samtec
MC4 MC5: library part 000583, Manufacturer=Molex
MC6: library part 002532, Manufacturer=Molex, Manufacturer_PN=0877585016
MH1 MH2 MH3 MH4: "Mounting hole", partnumber=ALIGNI_IGNORE
Q1 Q2 Q3 Q4: library part 002018, Manufacturer=Vishay
QSFP1 QSFP2 QSFP3 QSFP4: library part 001781, Manufacturer=Amphenol, Manufacturer_PN=U95-T111-1001
R1 R34 R54 R96 R103: library part 001521, "Thick-film resistor", Manufacturer=Vishay, Tolerance (%)=1, ValueFloat=10000
R2 R35 R55: library part 000964, "Thick-film resistor", Manufacturer=Vishay, Tolerance (%)=1, ValueFloat=200000
R3 R5 R6 R7 R8 R9 R68 R69 R73 R74 R76: library part 000755, Manufacturer=Vishay, ValueFloat=0, x_tolerance=1
R4 R12 R92 R102: library part 001162, "Thick-film resistor", Manufacturer=Vishay, Tolerance (%)=1, ValueFloat=2000
R10: library part 001910, "Thick-film resistor", Manufacturer=Vishay, Tolerance (%)=1, ValueFloat=5360
R11: library part 001007, "Thick-film resistor", Manufacturer=Vishay, Tolerance (%)=1, ValueFloat=4020
R13 R14 R15 R16 R17 R18 R19 R20 R21 R22 R23 R24 R28 R29 R30 R31 R32 R33 R36 R37 R38 R39 R40 R41 R42 R43 R44 R45 R46 R47 R48 R49 R50 R51 R52 R53 R56 R57 R58 R59 R60 R61 R62 R63 R80 R81 R82 R83 R84 R85 R86 R87 R88 R89 R90 R91: library part 001008, Manufacturer=Vishay, ValueFloat=4750, x_tolerance=1
R25 R26: library part 001126, Manufacturer=Vishay, ValueFloat=3010, x_tolerance=1
R27: library part 000927, "Thick-film resistor", Manufacturer=Vishay, Tolerance (%)=1, ValueFloat=2940
R64: library part 000969, Manufacturer=Vishay, ValueFloat=10, x_tolerance=1
R65: library part 000926, Manufacturer=Vishay, ValueFloat=107000, x_tolerance=1
R66: library part 000934, "Thick-film resistor", Manufacturer=Vishay, Tolerance (%)=1, ValueFloat=24900
R67: library part 001783, "Thick-film resistor", Manufacturer=Vishay, Tolerance (%)=1, ValueFloat=18700
R70: library part 001119, Manufacturer=Vishay, ValueFloat=23700, x_tolerance=1
R71: library part 002438, "NoLoad resistor", Manufacturer=Generic
R72 R75 R79: library part 001521, Manufacturer=Vishay, ValueFloat=10000, x_tolerance=1
R77: library part 001872, Manufacturer=Vishay, ValueFloat=121000, x_tolerance=1
R78: library part 002121, Manufacturer=Vishay, ValueFloat=22100, x_tolerance=1
R93 R94: library part 001919, "Thick-film resistor", Manufacturer=Vishay, Tolerance (%)=1, ValueFloat=5100
R95: library part 000826, "Thick-film resistor", Manufacturer=Vishay, Tolerance (%)=1, ValueFloat=12000
R97 R98 R99: library part 000755, "Thick-film resistor", Manufacturer=Vishay, Tolerance (%)=1, ValueFloat=0
R100 R101 R104: library part 001070, "Thick-film resistor", Manufacturer=Vishay, Tolerance (%)=1, ValueFloat=100000
S1: "Pushbutton", Manufacturer="Generic Components"
TP1 TP3 TP5 TP7 TP9 TP10 TP11 TP12 TP13 TP14: library part TP-PTH-65/100, "Test point, plated through-hole, 65/100mil", partnumber=ALIGNI_IGNORE
TP2 TP4 TP6 TP8 TP15 TP16 TP21 TP22: library part TP-PTH-25/45, "Test point, plated through-hole, 25/45mil"
TP17 TP18 TP19 TP20: library part TESTPOINT-SMD40, "Test point, surface-mount, 40mil"
TP23 TP24 TP25 TP26: "Test point, surface-mount, 20mil", partnumber=ALIGNI_IGNORE
U1 U4: library part 002434, Manufacturer=SiTime
U2: library part 002189, Manufacturer="ST Microelectronics"
U3 U5 U8: library part 002527, Manufacturer=NXP
U6 U7: library part 001712, Manufacturer="Silicon Labs"
U9: library part 002341, Manufacturer=Richtek
U10: library part 002118, "Step-down converter, 4.5 A, 7-18V input, 0.76-5.5V output, 4x4 mm", Manufacturer="Texas Instruments"
U11 U12: library part 002537, Manufacturer="ON Semiconductor"
U13 U15 U16 U17: library part 002400, "Level Translator, 0.65V - 3.6V, Direction Control", Manufacturer="Texas Instruments"
U14: library part 002398, Manufacturer=FTDI
U18: library part 002441, Manufacturer="Opal Kelly Incorporated"
U19: library part 001559, Manufacturer="ON Semiconductor"
Y1: library part 002402, "Crystal", Manufacturer=Abracon

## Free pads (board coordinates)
  round 20 hole 10 mask+2: ViaNoConnect1(-4793.25,4438.94) ViaNoConnect1(-4744.56,3906.99) ViaNoConnect1(-4707.95,4445.38)

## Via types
v1: diameter 20, hole 10, L1-TOP to L6-BOT, tented both sides, 957 vias
v2: diameter 18, hole 10, L1-TOP to L6-BOT, tented both sides, 786 vias

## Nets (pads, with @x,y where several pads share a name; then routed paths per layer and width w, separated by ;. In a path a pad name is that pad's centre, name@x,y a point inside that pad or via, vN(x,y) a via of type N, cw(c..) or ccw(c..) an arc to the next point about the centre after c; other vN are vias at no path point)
+1.8V: C4.2 C6.2 C27.2 C34.2 C51.2 C52.2 C59.2 C71.2 C75.2 C81.2 C128.2 J5.2 MC2.21 R3.2 R5.2 R6.2 TP3.1 U1.1 U1.6 U2.8 U4.1 U4.6 U6.1 U6.6 U7.1 U7.6 U13.6 U15.6 U16.6 U17.6 U19.1 U19.5 | length 3390.7
  L1-TOP w7: R6.2@1671.23,3443.67 1671.23,3445.64 1651.78,3465.08 1651.78,3530.28 ; R5.2@1671.23,3530.28 1651.78,3530.28 ; R3.2@1671.23,3616.9 1671.23,3614.93 1651.78,3595.48 1651.78,3530.28 ; U19.5@1940.16,3474.41 1940.16,3433.86 1956.69,3417.32 2076.04,3417.32
  L1-TOP w8: C128.2@1849.21,3561.42 1853.45,3557.18 1861.95,3557.18 1873.09,3546.05 1873.09,3518.47 1877.77,3513.78 U19.1@1892.52,3513.78 ; U15.6@2151.57,557.09 2152.76,558.27 2199.61,558.27 v1(2200.79,559.45) ; U16.6@2151.57,694.88 2152.76,696.06 2199.61,696.06 v1(2200.79,697.24) ; U13.6@2151.57,832.68 2152.76,833.86 2199.61,833.86 v1(2200.79,835.04) ; U17.6@2151.57,970.47 2152.76,971.65 2199.61,971.65 v1(2200.79,972.83)
  L1-TOP w10: v1(-3590.55,732.28) C34.2@-3590.55,704.72 -3548.23,704.72 U4.6@-3536.42,716.54 U4.1@-3536.42,653.54 ; U1.1@595.47,3236.22 U1.6@595.47,3173.23 625.98,3173.23 641.34,3188.58 C6.2@657.48,3188.58 v1(657.48,3149.21) ; U6.1@1005.91,3242.13 U6.6@1005.91,3167.32 1025.59,3167.32 1046.85,3188.58 C51.2@1070.87,3188.58 v1(1070.87,3161.42) ; v1(1244.09,3275.59) 1244.09,3358.07 1283.07,3397.05 C4.2@1283.07,3397.64 1283.07,3448.23 U2.8@1283.46,3448.62 ; U7.1@1407.48,3242.13 U7.6@1407.48,3167.32 1427.17,3167.32 1448.43,3188.58 C52.2@1472.44,3188.58 v1(1472.44,3161.42) ; C27.2@2174.02,1043.31 2421.26,1043.31 2448.82,1015.75 J5.2@2448.82,976.38
  L1-TOP w12: v1(-407.48,1624.02) MC2.21@-357.87,1624.02 v1(-309.06,1624.02)
  L1-TOP w15: v1(1606.3,3019.68) 1986.06,3019.68 2076.04,3109.66 2076.04,3417.32 2076.04,3538.13 2015.75,3598.43 1849.21,3598.43 ; R3.2@1671.23,3616.9 1764.99,3616.9 1783.46,3598.43 1849.21,3598.43 ; C128.2@1849.21,3561.42 1849.21,3598.43
  L1-TOP w20: v1(-431.1,1624.02) v1(-407.48,1624.02)
+3.3V_TST: C3.2 C8.2 C11.2 C12.2 C19.2 C20.2 C40.2 C41.2 C42.2 C43.2 C44.2 C45.2 C111.2 C112.2 C113.2 C114.2 C129.2 J3.40 J4.40 J6.40 J7.40 J14.40 L1.1 L2.1 L3.1 L4.1 L5.1 L6.1 L7.1 L8.1 L9.1 L10.1 L11.1 L12.1 L13.2 pad.ViaNoConnect1@-4744.56,3906.99 R1.2 R2.2 R19.2 R20.2 R21.2 R22.2 R23.2 R24.2 R25.2 R26.2 R28.2 R29.2 R34.2 R35.2 R42.2 R43.2 R44.2 R45.2 R46.2 R47.2 R52.2 R53.2 R54.2 R55.2 R65.2 R72.2 R80.2 R81.2 R82.2 R83.2 R84.2 R85.2 R86.2 R87.2 R88.2 R89.2 R90.2 R91.2 TP17.1 U11.1 U12.1 U19.8 | length 2039.6
  L1-TOP w6: R54.2@-4570.87,3271.65 -4523.62,3271.65 -4511.81,3259.84 v1(-4511.81,3236.22) ; v1(-4442.91,3364.17) R81.2@-4407.48,3364.17 R45.2@-4372.05,3364.17 R44.2@-4336.61,3364.17 R83.2@-4301.18,3364.17 R53.2@-4265.75,3364.17 R52.2@-4230.31,3364.17 ; R84.2@-4145.67,3192.91 v1(-4145.67,3228.35) ; R1.2@-3907.48,2842.52 R1.2@-3903.54,2842.52 -3860.24,2842.52 -3848.43,2830.71 v1(-3848.43,2811.02) R2.2@-3848.43,2807.09 ; R34.2@-3907.48,3265.75 R34.2@-3903.54,3265.75 -3860.24,3265.75 -3848.43,3253.94 v1(-3848.43,3234.25) R35.2@-3848.43,3230.31 ; v1(-3789.37,2938.98) R19.2@-3753.94,2938.98 R23.2@-3718.5,2938.98 R22.2@-3683.07,2938.98 R21.2@-3647.64,2938.98 R28.2@-3612.2,2938.98 R24.2@-3576.77,2938.98 ; v1(-3779.53,3362.2) R87.2@-3744.09,3362.2 R91.2@-3708.66,3362.2 R90.2@-3673.23,3362.2 R42.2@-3637.8,3362.2 R80.2@-3566.93,3362.2 ; R89.2@-3482.28,2763.78 R29.2@-3482.28,2799.21 v1(-3482.28,2834.65) ; R43.2@-3482.28,3190.94 v1(-3482.28,3226.38)
  L1-TOP w7: C45.2@-4421,3564.28 -4227.06,3564.28 -4169.29,3622.05 TP17.1@-4094.49,3622.05
  L1-TOP w8: v1(1900,3561.02) 1900,3542.91 1916.34,3526.57 U19.8@1916.34,3516.73
  L1-TOP w10: U11.1@-5522.77,2929.17 -5520.8,2927.2 -5487.34,2927.2 -5483.01,2922.87 C3.2@-5463.72,2922.87 -5463.52,2923.06 -5436.35,2923.06 v1(-5436.16,2923.26) ; C40.2@-4744.76,3907.19 -4715.52,3907.19 R65.2@-4710.44,3902.11 ; v1(1846.46,3059.06) 1846.26,3059.25 1846.26,3086.42 C8.2@1846.06,3086.61 1846.06,3105.91 1850.39,3110.24 1850.39,3143.7 U12.1@1852.36,3145.67
  L4-PWR w10: pad.ViaNoConnect1@-4744.56,3906.99 -4767.72,3883.84 -4767.72,3586.61 -4750.35,3569.24 v2(-4724.2,3569.24)
  other v1: 1983.07,3450.79 1983.07,3564.96 -4560.84,3893.67
  other v2: 201.56,894.79 246.24,894.79 290.93,894.79 335.61,894.79 380.3,894.79 424.98,894.79 201.56,938.09 246.24,938.09 290.93,938.09 335.61,938.09 380.3,938.09 424.98,938.09 -5032.48,2862.2 -4987.8,2862.2 -4943.11,2862.2 -4898.43,2862.2 -4853.74,2862.2 -4809.06,2862.2 -4402.56,2862.2 -4357.87,2862.2 -4313.19,2862.2 -4268.5,2862.2 -4223.82,2862.2 -4179.13,2862.2 -5032.48,2905.51 -4987.8,2905.51 -4943.11,2905.51 -4898.43,2905.51 -4853.74,2905.51 -4809.06,2905.51 -4402.56,2905.51 -4357.87,2905.51 -4313.19,2905.51 -4268.5,2905.51 -4223.82,2905.51 -4179.13,2905.51 201.56,3065.84 246.24,3065.84 290.93,3065.84 335.61,3065.84 380.3,3065.84 424.98,3065.84 201.56,3109.15 246.24,3109.15 290.93,3109.15 335.61,3109.15 380.3,3109.15 424.98,3109.15 -4647.2,3539.98 -4612.2,3539.98 -4724.2,3540.98 -4688.2,3540.98 -4572.2,3540.98 -4535.2,3540.98 -4461.2,3540.98 -4493.2,3541.98 -4493.2,3568.24 -4688.2,3569.24 -4572.2,3569.24 -4535.2,3569.24 -4461.2,3569.24 -4647.2,3570.24 -4612.2,3570.24 2213.87,4420.86 2236.87,4420.86 2260.87,4420.86 2283.87,4420.86 -4708.65,5364.01 -2858.26,5364.01 -929.12,5364.01 921.27,5364.01 -4708.65,5399.01 -2858.26,5399.01 -929.12,5399.01 921.27,5399.01 -4708.65,5434.01 -2858.26,5434.01 -929.12,5434.01 921.27,5434.01
+3.3V_TST_EN: R69.1 R74.1 U9.6 | length 246.3
  L1-TOP w6: U9.6@-4599.56,3749.98 -4588.99,3749.98 -4554.11,3784.86 -4554.11,3824.79 -4535.89,3843.02 -4535.89,3853.56 -4525.05,3864.39 -4495.72,3864.39 -4489.16,3870.95 -4489.16,3889.21 R74.1@-4489.2,3889.25 ; R74.1@-4489.94,3889.7 -4452.65,3889.7 R69.1@-4452.2,3889.25
+5V_TST: C49.2 C50.2 C54.2 J3.2 J4.2 J6.2 J7.2 J14.2 L14.2 pad.ViaNoConnect1@-4707.95,4445.38 pad.ViaNoConnect1@-4793.25,4438.94 R77.2 R79.2 TP19.1 U10.16 | length 1795.3
  L1-TOP w7: R79.2@-4834.94,4266.87 -4852.73,4266.87 -4862.2,4257.39 -4862.2,4122.05 -4779.53,4039.37 -4665.35,4039.37 -4649.91,4054.82 v2(-4649.91,4081.87) ; v2(-4602.17,4107.87) -4602.17,4054.92 -4586.7,4039.45 -4354.42,4039.45 -4196.85,3881.89 -4196.85,3802.63 -4173.75,3779.53 TP19.1@-4094.49,3779.53
  L1-TOP w8: R77.2@-4829.25,4438.55 -4793.65,4438.55 pad.ViaNoConnect1@-4793.25,4438.94
  L4-PWR w10: pad.ViaNoConnect1@-4793.25,4438.94 -4757.25,4402.94 -4757.25,4319.13 -4662.99,4224.87 v2(-4649.91,4224.87) ; pad.ViaNoConnect1@-4708.15,4445.18 -4640.57,4445.18 -4586.25,4390.87 v2(-4586.25,4224.87)
  other v2: 2214.56,3834.16 2237.56,3834.16 2261.56,3834.16 2284.56,3834.16 -4618.08,4081.87 -4586.25,4081.87 -4633.99,4107.87 -4649.91,4133.87 -4618.08,4133.87 -4586.25,4133.87 -4649.91,4172.87 -4618.08,4172.87 -4586.25,4172.87 -4633.99,4198.87 -4602.17,4198.87 -4618.08,4224.87 -4110.15,5364.01 -2259.76,5364.01 -330.62,5364.01 1519.77,5364.01 -4110.15,5399.01 -2259.76,5399.01 -330.62,5399.01 1519.77,5399.01 -4110.15,5434.01 -2259.76,5434.01 -330.62,5434.01 1519.77,5434.01
+5V_TST_EN: R75.1 R76.1 U10.6 | length 180
  L1-TOP w4.96: R76.1@-4831.42,4231.57 -4794.87,4231.57 v2(-4794.57,4231.87)
  L1-TOP w5: v2(-4794.57,4231.87) -4766.25,4231.87 -4753.25,4244.87 -4688.25,4244.87 -4682.09,4251.03 U10.6@-4682.09,4273.62
+5V_TST_PGOOD: R74.2 R79.1 TP20.1 U10.5 | length 1504
  L1-TOP w5: R79.1@-4795.57,4266.87 -4751.25,4266.87 -4744.5,4273.62 U10.5@-4707.68,4273.62
  L1-TOP w7: R79.1@-4795.57,4266.87 -4795.57,4268.83 -4819.36,4292.62 -4857.91,4292.62 -4881.89,4268.64 -4881.89,4086.61 -4808.07,4012.8 -4527.56,4012.8 ; R74.2@-4528.57,3889.25 -4528.57,4011.79 -4527.56,4012.8 ; TP20.1@-4094.49,3700.79 -4151.74,3700.79 -4228.35,3777.39 -4228.35,3866.14 -4375,4012.8 -4527.56,4012.8
+VDCIN: C1.1 C2.1 C28.1 C29.2 C35.2 C36.2 C37.2 C38.2 C47.2 C48.2 J1.1 J2.1 J2.2 J2.3 MC2.1 MC2.2 MC2.3 MC2.4 MC2.5 MC2.6 MC2.7 MC2.8 R4.2 R12.2 R69.2 R75.2 R92.2 R104.2 TP1.1 U9.5 U10.13 U10.14 U10.15 | length 792.3
  L1-TOP w6: v1(-3414.89,4823.73) -3414.12,4824.49 -3372.36,4824.49 -3314.96,4881.89 R12.2@-3314.96,4909.45 ; v1(-3055.12,4881.89) -2946.85,4881.89 -2923.23,4905.51 R92.2@-2921.26,4905.51
  L1-TOP w8: R69.2@-4412.83,3889.25 -4412.83,3820.34 C36.2@-4398.2,3805.72 ; v1(-4377.95,4818.9) R4.2@-4377.95,4842.52
  L3-PWR w6: v1(-3414.89,4823.73) -3152.65,4823.73 -3094.49,4881.89 v1(-3055.12,4881.89)
  other v1: -358.27,1173.23 -322.83,1173.23 -287.4,1173.23 -251.97,1173.23 -220.47,1173.23 -185.04,1173.23 -149.61,1173.23 -114.17,1173.23 -464.57,1216.54 -429.13,1216.54 -393.7,1216.54 -358.27,1216.54 -192.91,1216.54 -157.48,1216.54 -122.05,1216.54 -86.61,1216.54 -464.57,1251.97 -429.13,1251.97 -393.7,1251.97 -358.27,1251.97 -192.91,1251.97 -157.48,1251.97 -122.05,1251.97 -86.61,1251.97 -464.57,1287.4 -429.13,1287.4 -393.7,1287.4 -358.27,1287.4 -192.91,1287.4 -157.48,1287.4 -122.05,1287.4 -86.61,1287.4 -4553.27,3741.04
  other v2: -4511.62,3790.32 -4467.62,3790.32 -4420.41,3790.32 -4376.41,3790.32 -4329.25,3790.41 -4285.25,3790.41 -4511.2,3821.11 -4467.2,3821.11 -4419.99,3821.11 -4375.99,3821.11 -4328.83,3821.2 -4284.83,3821.2 -4794.57,4192.5 -4709.08,4473.87 -4677.25,4473.87 -4634.33,4473.87 -4709.08,4511.87 -4677.25,4511.87 -4645.43,4511.87 -4693.17,4537.87 -4661.34,4537.87 -4709.08,4563.87 -4677.25,4563.87 -4645.43,4563.87
B64_L1N: MC3.79 MC5.33 | length 6275.1
  L1-TOP w4.96: MC3.79@-1781.77,3979.65 MC3.79@-1781.5,3979.92 -1781.5,4027.82 v1(-1781.23,4028.09)
  L6-BOT w4.96: v1(-1781.23,4028.09) -1781.23,3913.07 -1822.77,3871.53 -1822.77,3819.7 -1846.75,3795.72 -1846.75,3600.55 -1675.03,3428.83 -1675.03,1847.52 -372.32,544.81 844.95,544.81 882.52,544.81 1062.99,364.34 1391.91,364.34 1497.24,259.01 1497.24,195.67 MC5.33@1535.43,157.48
B64_L1P: MC3.77 MC5.31 | length 6324.2
  L1-TOP w4.96: MC3.77@-1801.45,3979.65 -1801.72,3979.92 -1801.72,4081.25 v1(-1801.03,4081.95)
  L6-BOT w4.96: v1(-1801.03,4081.95) -1801.03,3917.26 -1839.73,3878.55 -1839.73,3826.72 -1863.71,3802.74 -1863.71,3593.53 -1691.99,3421.81 -1691.99,1840.5 -379.35,527.85 842.23,527.85 875.49,527.85 1055.97,347.38 1330.13,347.38 1418.5,259.01 1418.5,195.67 MC5.31@1456.69,157.48
B64_L5N: MC3.75 MC5.29 | length 6157.5
  L1-TOP w4.96: MC3.75@-1821.14,3979.65 MC3.75@-1820.87,3979.92 -1820.87,4027.82 v1(-1820.6,4028.09)
  L6-BOT w4.96: v1(-1820.6,4028.09) -1820.6,3921.68 -1856.7,3885.58 -1856.7,3833.75 -1880.67,3809.77 -1880.67,3586.5 -1708.95,3414.78 -1708.95,1833.47 -386.37,510.89 831.63,510.89 868.47,510.89 1048.94,330.42 1268.35,330.42 1339.76,259.01 1339.76,195.67 MC5.29@1377.95,157.48
B64_L5P: MC3.73 MC5.27 | length 6206.6
  L1-TOP w4.96: MC3.73@-1840.82,3979.65 -1841.09,3979.92 -1841.09,4081.25 v1(-1840.4,4081.95)
  L6-BOT w4.96: v1(-1840.4,4081.95) -1840.4,3931.26 -1897.64,3874.02 -1897.64,3579.47 -1725.92,3407.75 -1725.92,1826.44 -393.4,493.93 840.72,493.93 861.44,493.92 1041.91,313.45 1206.57,313.45 1261.02,259.01 1261.02,195.67 MC5.27@1299.21,157.48
B64_L6N: MC3.71 MC5.25 | length 6039.9
  L1-TOP w4.96: MC3.71@-1860.51,3979.65 MC3.71@-1860.24,3979.92 -1860.24,4027.82 v1(-1859.97,4028.09)
  L6-BOT w4.96: v1(-1859.97,4028.09) -1859.97,3935.68 -1914.6,3881.04 -1914.6,3815.81 -1914.6,3572.45 -1742.88,3400.73 -1742.88,1819.42 -400.43,476.96 854.42,476.96 1034.89,296.49 1144.8,296.49 1182.28,259.01 1182.28,195.67 MC5.25@1220.47,157.48
B64_L6P: MC3.69 MC5.23 | length 6089
  L1-TOP w4.96: MC3.69@-1880.19,3979.65 -1880.46,3979.92 -1880.46,4081.25 v1(-1879.77,4081.95)
  L6-BOT w4.96: v1(-1879.77,4081.95) -1879.77,3939.87 -1931.56,3888.07 -1931.56,3808.78 -1931.56,3565.42 -1759.84,3393.7 -1759.84,1812.39 -407.45,460 819.53,460 847.39,460 1027.86,279.53 1083.02,279.53 1103.54,259.01 1103.54,195.67 MC5.23@1141.73,157.48
B64_L7N: MC3.83 MC5.37 | length 6394.1
  L1-TOP w4.96: MC3.83@-1742.4,3979.65 MC3.83@-1742.13,3979.92 -1742.13,4027.82 v1(-1741.86,4028.09)
  L6-BOT w4.96: v1(-1741.86,4028.09) -1740.16,4026.39 -1740.16,3901.2 -1757.74,3883.62 -1757.74,3836.75 -1812.82,3781.67 -1812.82,3614.61 -1641.1,3442.89 -1641.1,1861.57 -358.27,578.74 870.08,578.74 896.57,578.74 1075.72,399.59 1514.14,399.59 1654.72,259.01 1654.72,195.67 MC5.37@1692.91,157.48
B64_L7P: MC3.81 MC5.35 | length 6441.7
  L1-TOP w4.96: MC3.81@-1762.08,3979.65 -1762.35,3979.92 -1762.35,4081.25 v1(-1761.66,4081.95)
  L6-BOT w4.96: v1(-1761.66,4081.95) -1761.66,3903.69 -1776.39,3888.95 -1776.39,3842.09 -1829.79,3788.69 -1829.79,3607.58 -1658.06,3435.86 -1658.06,1854.55 -365.29,561.78 855.55,561.78 889.55,561.78 1069.36,381.97 1453.02,381.97 1575.98,259.01 1575.98,195.67 MC5.35@1614.17,157.48
B64_L9N: MC3.68 MC5.26 | length 5534.4
  L1-TOP w4.96: MC3.68@-1899.61,3736.61 -1899.61,2809.53 -1406.68,2316.6 -1406.68,1597.39 -270.5,461.21 885.98,461.21 1050.73,296.46 1160.23,296.46 MC5.26@1220.47,236.22
B64_L9P: MC3.66 MC5.24 | length 5477.8
  L1-TOP w4.96: MC3.66@-1919.29,3736.61 -1919.29,2805.22 -1423.64,2309.57 -1423.64,1590.36 -277.53,444.25 870.71,444.25 878.95,444.25 1043.7,279.5 1098.45,279.5 MC5.24@1141.73,236.22
B64_L16N: MC3.76 MC5.34 | length 5760.5
  L1-TOP w4.96: MC3.76@-1820.87,3736.61 -1820.87,2826.74 -1338.83,2344.7 -1338.83,1625.5 -242.4,529.07 914.08,529.07 1078.83,364.31 1407.34,364.31 MC5.34@1535.43,236.22
B64_L16P: MC3.74 MC5.32 | length 5704
  L1-TOP w4.96: MC3.74@-1840.55,3736.61 -1840.55,2822.44 -1355.79,2337.68 -1355.79,1618.47 -249.43,512.1 885.53,512.1 907.05,512.1 1071.8,347.35 1345.56,347.35 MC5.32@1456.69,236.22
B64_L18N: MC3.72 MC5.30 | length 5647.4
  L1-TOP w4.96: MC3.72@-1860.24,3736.61 -1860.24,2818.13 -1372.75,2330.65 -1372.75,1611.44 -256.45,495.14 900.03,495.14 1064.78,330.39 1283.78,330.39 MC5.30@1377.95,236.22
B64_L18P: MC3.70 MC5.28 | length 5590.9
  L1-TOP w4.96: MC3.70@-1879.92,3736.61 -1879.92,2813.83 -1389.72,2323.63 -1389.72,1604.42 -263.48,478.18 852.53,478.18 893,478.18 1057.75,313.43 1222.01,313.43 MC5.28@1299.21,236.22
B64_L20N: MC3.80 MC5.38 | length 5873.6
  L1-TOP w4.96: MC3.80@-1781.5,3736.61 -1781.5,2835.35 -1573.84,2627.69 -1304.9,2358.76 -1304.9,1639.55 -228.35,562.99 929.5,562.99 1094.25,398.24 1530.89,398.24 MC5.38@1692.91,236.22
B64_L20P: MC3.78 MC5.36 | length 5817
  L1-TOP w4.96: MC3.78@-1801.18,3736.61 -1801.18,2831.05 -1321.87,2351.73 -1321.87,1632.52 -235.37,546.03 922.48,546.03 1087.23,381.28 1469.12,381.28 MC5.36@1614.17,236.22
B64_T0U_N12_VRP: MC3.33 MC5.21 | length 6187.2
  L1-TOP w4.96: MC3.33@-2431.1,3979.92 -2431.1,3899.61 -2413.39,3881.89 -2240.16,3881.89 -2192.91,3834.65 -2055.12,3834.65 -2039.37,3818.9 -2039.37,3650.28 v1(-1992.35,3603.26)
  L6-BOT w4.96: v1(-1992.35,3603.26) -1992.35,3602.22 -1776.81,3386.67 -1776.81,1805.36 -414.48,443.04 840.36,443.04 1024.39,259.01 1024.8,259.01 1024.8,195.67 MC5.21@1062.99,157.48
B68_L1N: MC1.108 MC4.28 | length 3974.7
  L1-TOP w4.96: MC4.28@-3976.38,236.22 -3856.13,356.47 -2948.88,356.47 -2410.41,894.94 -2410.41,2370.5 -2608.81,2568.9 -2935.44,2568.9 MC1.108@-2988.58,2568.9
B68_L1P: MC1.106 MC4.26 | length 4003.2
  L1-TOP w4.96: MC4.26@-4055.12,236.22 -3917.91,373.43 -2955.91,373.43 -2427.38,901.97 -2427.38,2363.47 -2613.12,2549.21 -2935.44,2549.21 MC1.106@-2988.58,2549.21
B68_L2N: MC1.104 MC4.24 | length 4031.6
  L1-TOP w4.96: MC4.24@-4133.86,236.22 -3979.68,390.39 -2962.94,390.39 -2444.34,908.99 -2444.34,2356.44 -2617.42,2529.53 -2935.44,2529.53 MC1.104@-2988.58,2529.53
B68_L2P: MC1.102 MC4.22 | length 4060
  L1-TOP w4.96: MC4.22@-4212.6,236.22 -4041.46,407.36 -2969.96,407.36 -2461.3,916.02 -2461.3,2349.42 -2621.73,2509.84 -2935.44,2509.84 MC1.102@-2988.58,2509.84
B68_L3N: MC1.88 MC4.8 | length 4259
  L1-TOP w4.96: MC4.8@-4763.78,236.22 -4473.9,526.1 -3019.15,526.1 -2580.04,965.2 -2580.04,2300.23 -2651.86,2372.05 -2935.44,2372.05 MC1.88@-2988.58,2372.05
B68_L3P: MC1.86 MC4.6 | length 4287.4
  L1-TOP w4.96: MC4.6@-4842.52,236.22 -4535.68,543.06 -3026.17,543.06 -2597.01,972.23 -2597.01,2293.21 -2656.16,2352.36 -2935.44,2352.36 MC1.86@-2988.58,2352.36
B68_L6N: MC1.100 MC4.20 | length 4088.4
  L1-TOP w4.96: MC4.20@-4291.34,236.22 -4103.24,424.32 -2976.99,424.32 -2478.26,923.05 -2478.26,2342.39 -2626.03,2490.16 -2935.44,2490.16 MC1.100@-2988.58,2490.16
B68_L6P: MC1.98 MC4.18 | length 4116.9
  L1-TOP w4.96: MC4.18@-4370.08,236.22 -4165.02,441.28 -2984.02,441.28 -2495.23,930.07 -2495.23,2335.36 -2630.33,2470.47 -2935.44,2470.47 MC1.98@-2988.58,2470.47
B68_L7N: MC1.72 MC4.31 | length 3286.7
  L1-TOP w4.96: MC1.72@-2988.58,2214.57 v1(-2761.81,2214.57)
  L6-BOT w4.96: MC4.31@-3818.9,157.48 -3780.7,195.67 -3780.7,259.01 -3683.53,356.18 -2992.64,356.18 -2568.39,780.43 -2568.39,1990.85 -2731.52,2153.98 -2731.52,2184.28 v1(-2761.81,2214.57)
B68_L7P: MC1.70 MC4.29 | length 3297.4
  L1-TOP w4.96: MC1.70@-2988.58,2194.88 v1(-2809.06,2194.88)
  L6-BOT w4.96: MC4.29@-3897.64,157.48 -3859.44,195.67 -3859.44,259.01 -3745.31,373.15 -2999.66,373.15 -2585.35,787.46 -2585.35,1983.83 -2770.82,2169.29 -2783.46,2169.29 v1(-2809.06,2194.88)
B68_L8N: MC1.80 MC4.39 | length 3195.5
  L1-TOP w4.96: MC1.80@-2988.58,2293.31 v1(-2742.13,2293.31)
  L6-BOT w4.96: MC4.39@-3503.94,157.48 -3095.38,157.48 -2500.54,752.33 -2500.54,2018.96 -2642.36,2160.79 -2642.36,2268.41 -2684.6,2310.65 -2724.78,2310.65 v1(-2742.13,2293.31)
B68_L8P: MC1.78 MC4.37 | length 3239.7
  L1-TOP w4.96: MC1.78@-2988.58,2273.62 v1(-2718.5,2273.62)
  L6-BOT w4.96: MC4.37@-3582.68,157.48 -3544.48,195.67 -3544.48,259.01 -3498.2,305.29 -2971.56,305.29 -2517.5,759.35 -2517.5,2011.93 -2659.33,2153.76 -2659.33,2249.46 -2683.48,2273.62 v1(-2718.5,2273.62)
B68_L9N: MC1.67 MC4.15 | length 3972.8
  L1-TOP w4.96: v1(-3333.92,2175.89) -3333.22,2175.2 MC1.67@-3231.89,2175.2 MC1.67@-3231.62,2175.47
  L6-BOT w4.96: MC4.15@-4448.82,157.48 -4410.63,195.67 -4410.63,259.01 -4177.75,491.89 -3048.85,491.89 -2704.09,836.64 -2704.09,1899.21 -2838.37,2033.48 -2838.73,2033.48 -2838.88,2033.63 -3029.7,2033.63 -3084.88,2088.82 -3151.81,2088.82 -3238.88,2175.89 v1(-3333.92,2175.89)
B68_L9P: MC1.65 MC4.13 | length 3893.2
  L1-TOP w4.96: v1(-3280.05,2155.78) -3279.78,2155.51 MC1.65@-3231.89,2155.51 MC1.65@-3231.62,2155.24
  L6-BOT w4.96: MC4.13@-4527.56,157.48 -4489.37,195.67 -4489.37,259.01 -4239.52,508.85 -3055.87,508.85 -2721.06,843.67 -2721.06,1892.18 -2845.39,2016.52 -2845.76,2016.52 -2845.91,2016.67 -3040.29,2016.67 -3094.49,2070.87 -3165.35,2070.87 -3250.27,2155.78 v1(-3280.05,2155.78)
B68_L10N: MC1.64 MC4.23 | length 3382.6
  L1-TOP w4.96: MC1.64@-2988.58,2135.83 -2988.24,2135.49 -2893.81,2135.49 v1(-2893.47,2135.15)
  L6-BOT w4.96: MC4.23@-4133.86,157.48 -4095.67,195.67 -4095.67,259.01 -3930.64,424.04 -3020.74,424.04 -2636.24,808.54 -2636.24,1962.75 -2733.35,2059.86 -2791.9,2118.4 -2876.73,2118.4 v1(-2893.47,2135.15)
B68_L10P: MC1.62 MC4.21 | length 3411.1
  L1-TOP w4.96: MC1.62@-2988.55,2116.18 v1@-2943.11,2116.18
  L6-BOT w4.96: MC4.21@-4212.6,157.48 -4174.41,195.67 -4174.41,259.01 -3992.41,441 -3027.77,441 -2653.2,815.56 -2653.2,1955.72 -2750.32,2052.83 -2796.21,2098.73 -2925.59,2098.73 v1(-2943.07,2116.21)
